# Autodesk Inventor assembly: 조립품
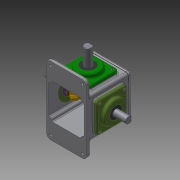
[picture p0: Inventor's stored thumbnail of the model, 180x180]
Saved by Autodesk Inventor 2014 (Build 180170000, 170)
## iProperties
Created: 2019-04
Part Number: 조립품
Document SubType Name: Assembly
Designer: kh
Mass: 2475.38 g
Surface Area: 2640.96 cm^2
Volume: 832.515 cm^3
Density: 2.97338 g/cm^3
Author: kh
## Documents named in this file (16)
- C:\Users\kh\Desktop\390407v1014\조립품.iam
- C:\Users\kh\Desktop\390407v1014\본체.ipt
- C:\Users\kh\Desktop\390407v1014\메인커버.ipt
- C:\Users\kh\Desktop\390407v1014\서브커버.ipt
- C:\Users\kh\Desktop\390407v1014\베어링 6204.ipt
- C:\Users\kh\Desktop\390407v1014\베어링 6203.ipt
- C:\Users\kh\Desktop\390407v1014\메인축.ipt
- C:\Users\kh\Desktop\390407v1014\키 4x4.ipt
- C:\Users\kh\Desktop\390407v1014\메인베벨기어.ipt
- C:\Users\kh\Desktop\390407v1014\오일 실 20 35 8.ipt
- C:\Users\kh\Desktop\390407v1014\서브축.ipt
- C:\Users\kh\Desktop\390407v1014\서브베벨기어.ipt
- C:\Users\kh\Desktop\390407v1014\오일 실 17 32 8.ipt
- C:\Users\kh\Desktop\390407v1014\개스킷.ipt
- C:\Users\kh\Desktop\390407v1014\상부커버.ipt
- C:\Users\kh\Desktop\390407v1014\볼트 M4.ipt
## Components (1 placed, 1 different names)
1. 개스킷:1
